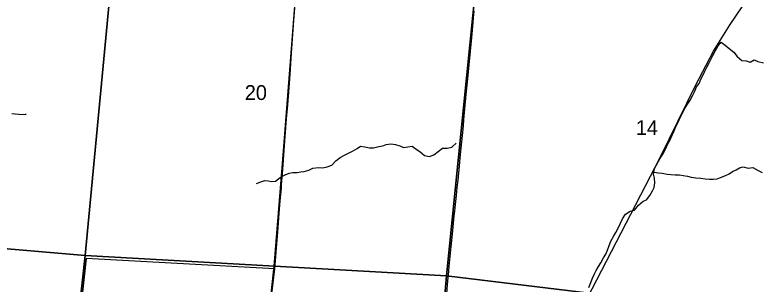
# Model space of a CAD drawing. Extents: x 0 to 1101, y 0 to 440.
# Drawn here: x 840.461 to 842.57, y 369.787 to 370.546 of the extents above; entities that cross this region are included whole.
import ezdxf

# ---------------------------------------------------------------- set-up
doc = ezdxf.new("R2010")
doc.units = 0
for name, color, linetype in [('GM_X_Corporation', 7, 'Continuous'), ('GM_X_Minor_River', 7, 'Continuous'), ('GM_X_Rail_Line', 7, 'Continuous'), ('GM_X_Section', 7, 'Continuous'), ('GM_X_Section_Text', 7, 'Continuous'), ('GM_X_Township_Road', 7, 'Continuous'), ('GM_X_US_Route', 7, 'Continuous')]:
    doc.layers.add(name, color=color, linetype=linetype)

msp = doc.modelspace()

# ---------------------------------------------------------------- linework, layer by layer
at = {"layer": 'GM_X_Corporation'}
msp.add_lwpolyline([(841.1666, 369.5856), (841.1939, 369.8301), (840.6616, 369.8589), (840.6081, 369.3662)], dxfattribs=at)
at = {"layer": 'GM_X_Minor_River'}
for points in [[(842.0805, 369.7768), (842.086, 369.7908), (842.0912, 369.8036), (842.097, 369.8153), (842.1017, 369.8255), (842.1083, 369.8364), (842.1146, 369.8466), (842.122, 369.8613), (842.129, 369.8715), (842.1333, 369.8824), (842.138, 369.8957), (842.1431, 369.9078), (842.1509, 369.9225), (842.1568, 369.9326), (842.165, 369.9481), (842.1704, 369.9583), (842.1759, 369.9711), (842.1841, 369.9843), (842.1971, 369.9929), (842.2093, 369.9957), (842.2213, 370.0092), (842.2336, 370.0212), (842.2431, 370.0245), (842.2532, 370.0365), (842.2606, 370.0497), (842.2653, 370.0595), (842.267, 370.0724), (842.266, 370.0857), (842.2635, 370.0972), (842.2664, 370.1116), (842.2703, 370.1214), (842.2777, 370.1334), (842.2836, 370.1448), (842.291, 370.1561), (842.2968, 370.1677), (842.3031, 370.1806), (842.3089, 370.1923), (842.316, 370.2066), (842.3203, 370.2168), (842.3242, 370.2266), (842.3313, 370.2402), (842.336, 370.25), (842.3406, 370.2598), (842.3457, 370.2708), (842.3528, 370.2844), (842.359, 370.2945), (842.3667, 370.3058), (842.3734, 370.3179), (842.3788, 370.3296), (842.3847, 370.3435), (842.3921, 370.3533), (842.3972, 370.3646), (842.4031, 370.3771), (842.4078, 370.388), (842.414, 370.3986), (842.4195, 370.4092), (842.425, 370.4209), (842.4308, 370.4318), (842.4382, 370.4457), (842.4456, 370.4593), (842.4545, 370.4694), (842.4658, 370.4606), (842.477, 370.452), (842.4898, 370.4412), (842.4995, 370.4286), (842.5126, 370.4181), (842.5244, 370.4172), (842.5365, 370.4133), (842.5476, 370.4199), (842.5578, 370.4152), (842.574, 370.4112)], [(840.4517, 370.2686), (840.4615, 370.2672), (840.4717, 370.2661), (840.4922, 370.2655), (840.4907, 370.2659)], [(841.1428, 370.0703), (841.1554, 370.0754), (841.1661, 370.0794), (841.1755, 370.0786), (841.1861, 370.0761), (841.1964, 370.0775), (841.2098, 370.0876), (841.2236, 370.095), (841.2347, 370.1002), (841.2454, 370.1019), (841.2579, 370.1017), (841.2674, 370.1031), (841.2773, 370.1045), (841.2906, 370.1085), (841.3021, 370.1137), (841.3177, 370.1157), (841.3298, 370.1152), (841.342, 370.1173), (841.3557, 370.1224), (841.3662, 370.1345), (841.3785, 370.1438), (841.3888, 370.1493), (841.3987, 370.1545), (841.414, 370.1619), (841.4267, 370.1697), (841.4366, 370.176), (841.448, 370.174), (841.4612, 370.1712), (841.4734, 370.171), (841.4879, 370.1746), (841.4989, 370.1771), (841.5084, 370.1804), (841.5221, 370.1825), (841.5354, 370.1808), (841.5475, 370.1768), (841.5573, 370.1725), (841.5699, 370.1742), (841.582, 370.176), (841.5937, 370.1675), (841.6038, 370.1609), (841.6173, 370.1497), (841.6314, 370.1472), (841.6436, 370.1516), (841.6551, 370.1609), (841.6674, 370.1706), (841.6807, 370.1705), (841.694, 370.1733), (841.7059, 370.1849)], [(842.2646, 370.1024), (842.2773, 370.1004), (842.2875, 370.0995), (842.3019, 370.097), (842.3121, 370.0957), (842.3239, 370.0952), (842.3364, 370.095), (842.3474, 370.0934), (842.3591, 370.0913), (842.3693, 370.0889), (842.383, 370.0864), (842.3966, 370.0855), (842.4091, 370.0838), (842.4209, 370.0825), (842.4315, 370.0827), (842.4429, 370.0837), (842.4525, 370.0874), (842.4647, 370.0921), (842.4769, 370.0977), (842.4865, 370.1044), (842.4964, 370.1096), (842.506, 370.1151), (842.5167, 370.1173), (842.5303, 370.1137), (842.5436, 370.1158), (842.5587, 370.1072), (842.57, 370.1021)]]:
    msp.add_lwpolyline(points, dxfattribs=at)
at = {"layer": 'GM_X_Rail_Line'}
for points in [[(841.0634, 368.7492), (841.0752, 368.8127), (841.0841, 368.8787), (841.1281, 369.2523), (841.1581, 369.5196), (841.193, 369.8378), (841.2158, 370.1274), (841.272, 370.836), (841.3678, 371.852), (841.4644, 372.7575), (841.4712, 372.8458), (841.5195, 373.3971), (841.577, 374.1201)], [(841.4728, 368.6426), (841.5036, 368.6835), (841.5374, 368.7376), (841.6188, 368.8614), (841.6632, 368.9407), (841.7044, 369.0211), (841.7667, 369.1427), (842.0077, 369.6134), (842.282, 370.1444), (842.3817, 370.3472), (842.4321, 370.4445), (842.4792, 370.5194), (842.5317, 370.5965), (842.5789, 370.6613), (842.6287, 370.7304), (842.8514, 370.9969), (843.1012, 371.295), (843.5697, 371.844), (844.1633, 372.5544), (844.2567, 372.6675)]]:
    msp.add_lwpolyline(points, dxfattribs=at)
at = {"layer": 'GM_X_Section'}
for points in [[(839.7037, 370.9776), (840.7556, 370.8893), (840.6594, 369.8677), (839.6271, 369.9558)], [(840.7556, 370.8893), (841.7775, 370.7877), (841.6791, 369.8096), (840.6594, 369.8677)], [(842.8172, 370.6809), (842.711, 369.6847), (841.6791, 369.8096), (841.7775, 370.7877)], [(840.6594, 369.8677), (840.5498, 368.8732), (839.5518, 368.9699), (839.6271, 369.9558)], [(840.6594, 369.8677), (841.6791, 369.8096), (841.5895, 368.7863), (840.5498, 368.8732)], [(842.711, 369.6847), (842.6097, 368.6878), (841.5895, 368.7863), (841.6791, 369.8096)]]:
    msp.add_lwpolyline(points, close=True, dxfattribs=at)
at = {"layer": 'GM_X_Township_Road'}
for points in [[(841.6842, 369.8119), (841.6865, 369.836), (841.6904, 369.8741), (841.6923, 369.8929), (841.6957, 369.9275), (841.7008, 369.9795), (841.7021, 369.9924), (841.7041, 370.011), (841.707, 370.0369), (841.7094, 370.0598), (841.7115, 370.0802), (841.7145, 370.1105), (841.7186, 370.1525), (841.724, 370.2063), (841.7265, 370.2329), (841.7282, 370.2508), (841.7348, 370.3214), (841.7399, 370.3752), (841.7428, 370.4055), (841.7466, 370.4442), (841.7504, 370.4828), (841.754, 370.5249), (841.7553, 370.5387), (841.7573, 370.5571)], [(841.6264, 369.1614), (841.6271, 369.1698), (841.6295, 369.1976), (841.6318, 369.2261), (841.6357, 369.2707), (841.6379, 369.2946), (841.6394, 369.3107), (841.6409, 369.3286), (841.6454, 369.3831), (841.6505, 369.4443), (841.6529, 369.4746), (841.6549, 369.5002), (841.6573, 369.53), (841.6605, 369.5691), (841.6646, 369.609), (841.6678, 369.64), (841.6714, 369.6783), (841.6766, 369.7302), (841.6795, 369.7606), (841.6827, 369.7958), (841.6842, 369.8119)]]:
    msp.add_lwpolyline(points, dxfattribs=at)
at = {"layer": 'GM_X_US_Route'}
for points in [[(841.1944, 369.8295), (841.1985, 369.8768), (841.2032, 369.9332), (841.2069, 369.9859), (841.2097, 370.0218), (841.213, 370.0571), (841.2129, 370.0577), (841.2135, 370.0645), (841.2135, 370.0664), (841.2151, 370.0881), (841.2167, 370.1098), (841.2219, 370.1779), (841.2277, 370.2535), (841.23, 370.2814), (841.2338, 370.3285), (841.2376, 370.3793), (841.2417, 370.4382), (841.2484, 370.5309), (841.2535, 370.6019)], [(841.167, 369.585), (841.1695, 369.6082), (841.1711, 369.623), (841.1768, 369.6737), (841.187, 369.767), (841.1944, 369.8295)]]:
    msp.add_lwpolyline(points, dxfattribs=at)

# ---------------------------------------------------------------- texts
at = {"layer": 'GM_X_Section_Text'}
for s, p in [('20', (841.1097, 370.3063)), ('14', (842.2135, 370.2074))]:
    msp.add_text(s, height=0.04186, rotation=0, dxfattribs=at).set_placement(p)

doc.saveas('drawing.dxf')
